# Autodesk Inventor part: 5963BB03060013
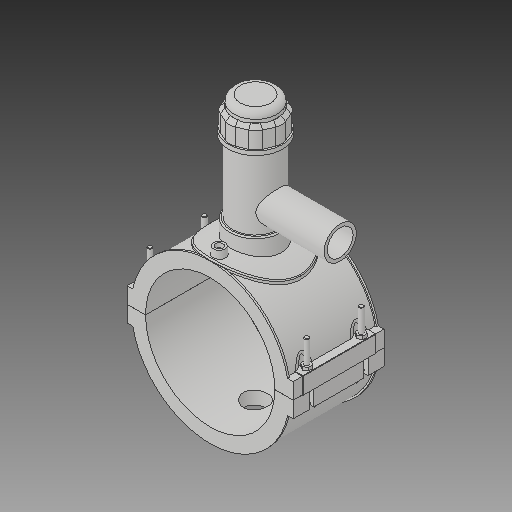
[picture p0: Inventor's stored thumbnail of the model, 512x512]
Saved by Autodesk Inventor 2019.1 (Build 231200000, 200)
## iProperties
Created: 2017-07
Part Number: 5963BB03060013
Material: Generic
Description: PLASSON TAPPING SADDLE 6''IPS x 1 1/4''IPS
Document SubType Name: Modeling
Designer: KIM
Mass: 1712.7 g
Surface Area: 2671.49 cm^2
Volume: 1712.7 cm^3
Density: 1 g/cm^3
Appearance: Default
Author: KIM
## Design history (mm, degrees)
derived "5963B.ipt"
feature "Solid1::5963B.ipt"
feature "Solid2::5963B.ipt"
feature "Solid4::5963B.ipt"
feature "Solid5::5963B.ipt"
tag "TaggingFeature1"
body "Solid1"
body "Solid2"
other parameters: "d_" = 168, "B_" = 215.9, "L_" = 118.11, "d_t" = 6, "H_2" = 177.038, "H_1" = 65.024, "d_1" = 42.1, "H_" = 109.982, "d1" = 201.6, "d148" = 2.52, "d160" = 2.52, "d169" = 3.2805, "d192" = 6.1236, "d0" = 168, "d2" = 215.9, "d3" = 42, "d4" = 118.11, "d5" = 0, "d6" = 0.1, "d8" = 0, "d19" = 6, "d20" = 6, "d21" = 70.866, "d23" = 0, "d24" = 35.433, "d26" = 0, "d29" = 3, "d30" = 56, "d31" = 6, "d32" = 0, "d33" = 0, "d34" = 0.6, "d40" = 104.832, "d41" = 117.6, "d43" = 0, "d45" = 0, "d47" = 171.666, "d70" = 15, "d72" = 0, "d73" = 6, "d75" = 5, "d76" = 0, "d77" = 8.4, "d78" = 114, "d79" = 15, "d80" = 47.244, "d82" = 5 deg, "d84" = 4, "d85" = 14, "d86" = 0, "d87" = 3, "d88" = 0, "d89" = 1, "d90" = 1, "d91" = 94.488, "d92" = 0, "d93" = 0.5, "d94" = 88.42105, "d96" = 205.632, "d97" = 2.3622, "d98" = 0, "d102" = 1.68, "d120" = 140 deg, "d121" = 24.228, "d122" = 20 deg, "d123" = 403.2, "d124" = 120.96, "d126" = 0, "d143" = 173.04, "d145" = 25.84615, "d149" = 2.52, "d150" = 28.43077, "d153" = 118.11, "d154" = 0, "d156" = 100.8, "d157" = 160 deg, "d159" = 6.72, "d161" = 2.52, "d162" = 70.866, "d163" = 0, "d164" = 84, "d167" = 16.8, "d168" = 98.34146, "d170" = 3.2805, "d172" = 0, "d173" = 1, "d175" = 84, "d176" = 20 deg, "d177" = 11.76, "d178" = 33.6, "d180" = 0, "d183" = 13.44, "d184" = 9.408, "d185" = 38.38575, "d186" = 38.38575, "d187" = 100.8, "d188" = 10.08, "d189" = 11.76, "d190" = 0, "d191" = 151.2, "d193" = 6.1236, "d194" = 4.13385, "d195" = 90 deg, "d197" = 0, "d199" = 0, "d200" = 16.8, "d202" = 0, "d203" = 177.038, "d204" = 67.032, "d205" = 49.392, "d206" = 59.976, "d207" = 132.7785, "d208" = 138.08964, "d209" = 164.64534, "d210" = 60.6816, "d211" = 70.56, "d212" = 56.448, "d213" = 39.5766, "d216" = 0, "d217" = 16.8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
